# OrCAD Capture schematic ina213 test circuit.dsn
size A
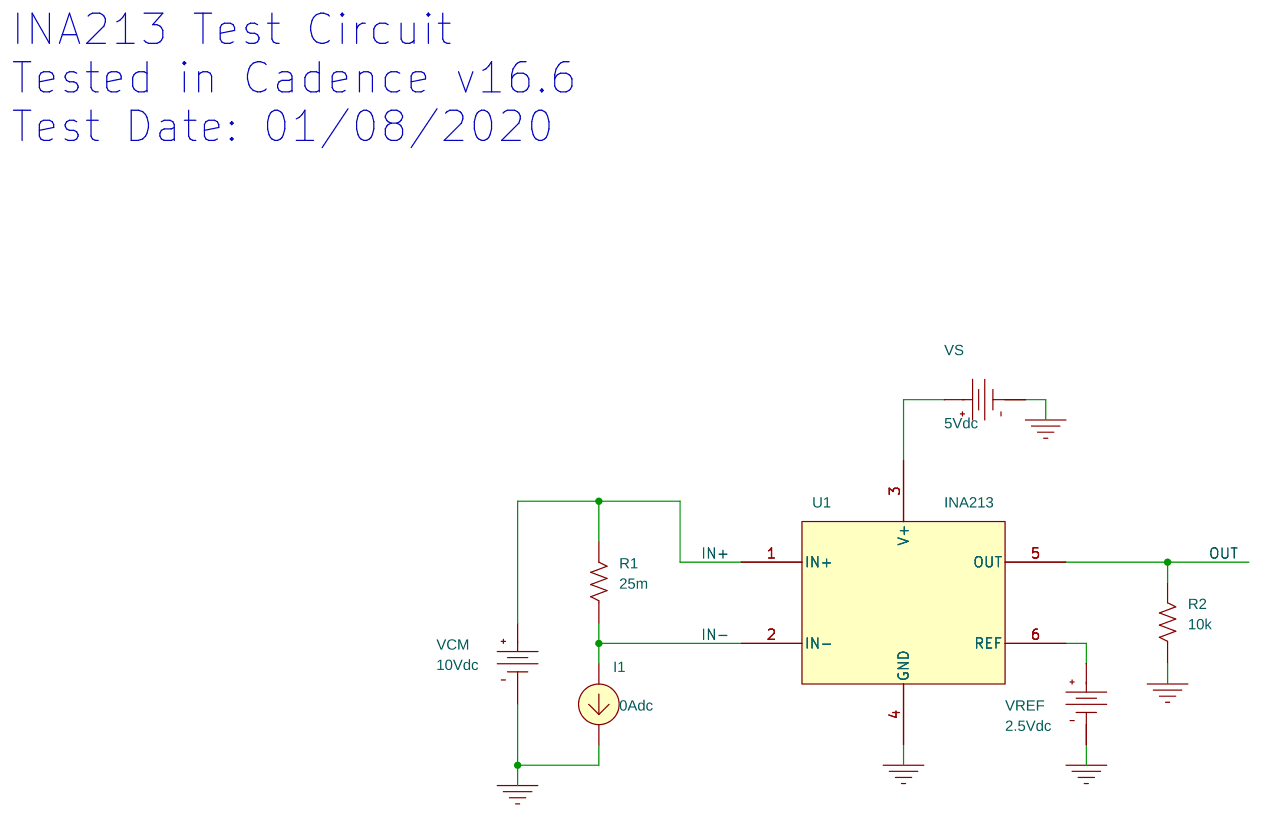
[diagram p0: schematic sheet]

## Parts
I1  IDC
R1  25m  [AX/RC05]
R2  10k  [AX/RC05]
U1  INA213
VCM  VDC
VREF  VDC
VS  VDC

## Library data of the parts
I1 = IDC: DC: 0Adc
R1 R2 = R
U1 = INA213
VCM = VDC: DC: 10Vdc
VREF = VDC: DC: 2.5Vdc
VS = VDC: DC: 5Vdc

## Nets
0: I1.2(-) R2.1 U1.4(GND) VCM.1(-) VREF.1(-) VS.1(-)
IN+: R1.2 U1.1(IN+) VCM.0(+)
IN-: I1.1(+) R1.1 U1.2(IN-)
OUT: R2.2 U1.5(OUT)
N01064: U1.3(V+) VS.0(+)
N01457: U1.6(REF) VREF.0(+)

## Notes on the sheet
- INA213 Test Circuit
  Tested in Cadence v16.6
  Test Date: 01/08/2020
